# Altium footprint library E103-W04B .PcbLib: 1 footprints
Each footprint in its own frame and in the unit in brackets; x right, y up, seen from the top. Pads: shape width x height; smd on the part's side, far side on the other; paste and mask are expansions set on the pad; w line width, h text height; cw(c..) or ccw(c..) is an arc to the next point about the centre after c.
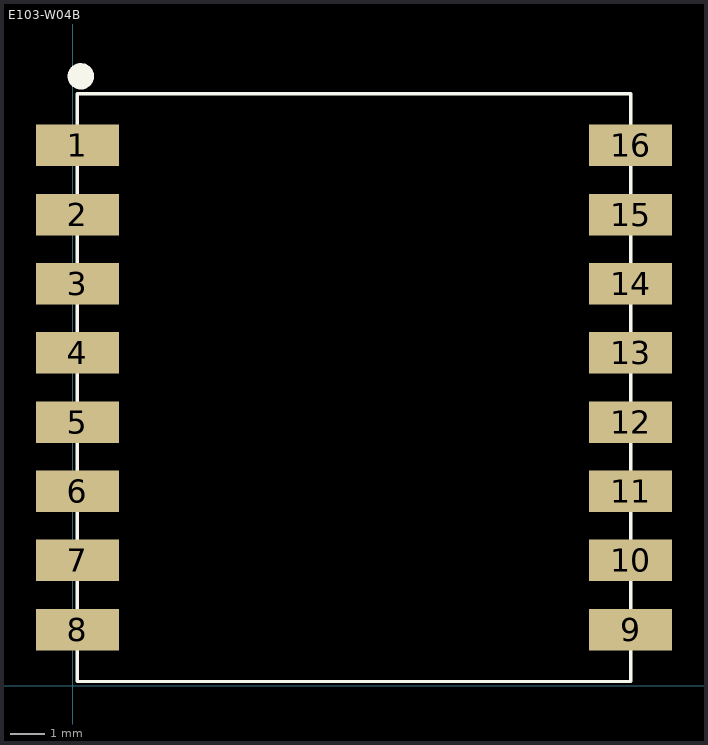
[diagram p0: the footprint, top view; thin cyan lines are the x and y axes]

## E103-W04B [mm]
pads (16):
  rect 2.4x1.2 smd: 1(0.127,15.627) 2(0.127,13.627) 3(0.127,11.627) 4(0.127,9.627) 5(0.127,7.627) 6(0.127,5.627) 7(0.127,3.627) 8(0.127,1.627) 9(16.127,1.627) 10(16.127,3.627) 11(16.127,5.627) 12(16.127,7.627) 13(16.127,9.627) 14(16.127,11.627) 15(16.127,13.627) 16(16.127,15.627)
Top Overlay:
  circle w0.2: c0.227,17.627 r0.283
  circle w0.2: c0.227,17.627 r0.1
  lines w0.1: 0.127,0.127 16.127,0.127 16.127,17.127 0.127,17.127 0.127,0.127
